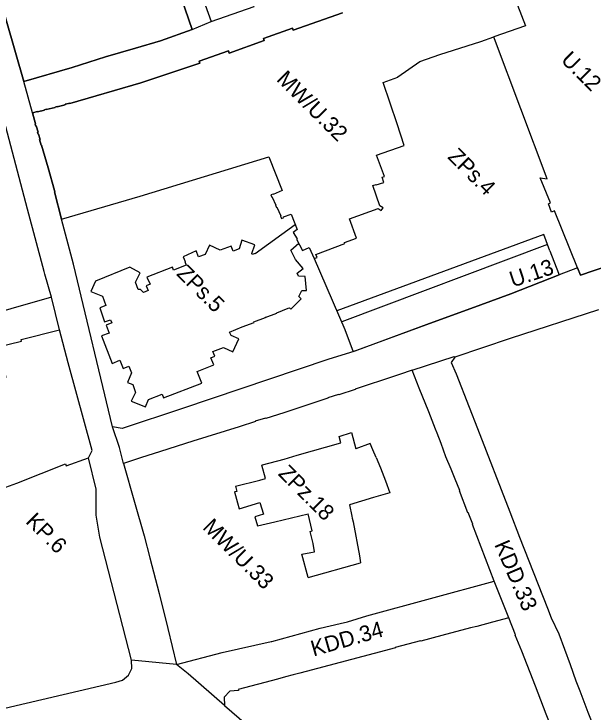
# Model space of a CAD drawing. Extents: x 7423835 to 7425280, y 5546086 to 5547600.
# Drawn here: x 7424373.9 to 7424593.5, y 5546340.4 to 5546605 of the extents above; entities that cross this region are included whole.
import ezdxf

# ---------------------------------------------------------------- set-up
doc = ezdxf.new("R2010")
doc.units = 0
for name, color, linetype in [('linie rozgraniczające', 7, 'Continuous'), ('nieprzekraczalne linie zabudowy', 7, 'Continuous'), ('obowiazujace linie zabudowy', 7, 'Continuous'), ('przeznaczenia terenów', 7, 'Continuous')]:
    doc.layers.add(name, color=color, linetype=linetype)

msp = doc.modelspace()

# ---------------------------------------------------------------- linework, layer by layer
at = {"layer": 'linie rozgraniczające'}
for p, q in [((7424441.46, 5546599.12), (7424448.69, 5546602.18)), ((7424380.94, 5546567.54), (7424377.65, 5546579.36)), ((7424587.64, 5546508.75), (7424580.62, 5546506.1)), ((7424524.96, 5546469.95), (7424540.84, 5546475.2)), ((7424540.84, 5546475.2), (7424541.11, 5546474.97)), ((7424527.63, 5546463.24), (7424524.96, 5546469.95)), ((7424485.48, 5546391.4), (7424505.36, 5546397.02)), ((7424561.54, 5546376.13), (7424556.04, 5546390.02)), ((7424435.51, 5546358.4), (7424418.49, 5546360.03))]:
    msp.add_line(p, q, dxfattribs=at)
for points in [[(7424498.22, 5546619.84), (7424492.5, 5546638.34), (7424492.84, 5546638.45), (7424491.5, 5546642.95), (7424486.43, 5546660.24), (7424483.37, 5546671.92), (7424480.11, 5546679.93), (7424468.32, 5546674.65), (7424455.33, 5546669.86), (7424428.5, 5546660.01), (7424437.17, 5546634.91), (7424441.77, 5546621.66), (7424448.69, 5546602.18), (7424464.99, 5546607.91), (7424464.93, 5546608.08), (7424487.47, 5546615.94)], [(7424415.44, 5546675.99), (7424420.93, 5546660.04), (7424421.75, 5546657.53), (7424423.79, 5546651.25), (7424427.88, 5546638.9), (7424441.46, 5546599.12), (7424429.54, 5546594.89), (7424419.97, 5546592.1), (7424408.6, 5546588.75), (7424395.96, 5546584.68), (7424377.65, 5546579.36), (7424357.5, 5546649.05), (7424367.44, 5546652.38), (7424372.88, 5546654.73), (7424377.74, 5546656.83), (7424384.62, 5546660.5)], [(7424557.12, 5546627.37), (7424559.4, 5546620.71), (7424560.48, 5546617.76), (7424561.25, 5546618.02), (7424567.94, 5546600.51), (7424555.92, 5546596.35)], [(7424391.99, 5546527.21), (7424389.27, 5546537.66), (7424389.42, 5546537.7), (7424389.3, 5546538.14), (7424386.83, 5546546.71), (7424384.36, 5546555.27), (7424384.22, 5546555.23), (7424383.61, 5546557.45), (7424383.8, 5546557.5), (7424383.2, 5546559.5), (7424383.06, 5546559.46), (7424382.86, 5546560.15), (7424383.05, 5546560.2), (7424382.33, 5546562.56), (7424382.22, 5546562.53), (7424382, 5546563.3), (7424382.12, 5546563.33), (7424380.94, 5546567.54), (7424382.81, 5546568.01), (7424382.85, 5546567.88), (7424385.46, 5546568.58), (7424385.43, 5546568.73), (7424386.13, 5546568.89), (7424386.17, 5546568.76), (7424389.56, 5546569.61), (7424389.53, 5546569.75), (7424390.24, 5546569.93), (7424390.27, 5546569.8), (7424393.37, 5546570.63), (7424393.33, 5546570.77), (7424394.59, 5546571.11), (7424395.05, 5546571.23), (7424395.09, 5546571.09), (7424422, 5546578.95), (7424444.35, 5546586.36), (7424444.17, 5546587.18), (7424455.24, 5546591.04), (7424455.47, 5546590.17), (7424468.84, 5546594.96), (7424468.57, 5546595.67), (7424479.54, 5546599.6), (7424479.78, 5546598.91), (7424498.49, 5546605.47)], [(7424391.99, 5546527.21), (7424421.79, 5546535.98), (7424470.55, 5546550.9), (7424470.55, 5546550.9), (7424475.58, 5546538.13), (7424472.2, 5546536.65), (7424472.15, 5546536.77), (7424471.31, 5546536.41), (7424471.7, 5546535.56), (7424471.81, 5546535.61), (7424473.2, 5546532.59), (7424473.1, 5546532.55), (7424473.47, 5546531.71), (7424473.59, 5546531.74), (7424475.09, 5546528.46), (7424474.98, 5546528.41), (7424475.37, 5546527.53), (7424476.25, 5546527.88), (7424476.16, 5546528.09), (7424479.01, 5546529.16), (7424481.31, 5546523.3), (7424479.78, 5546522.15), (7424481.34, 5546519.74), (7424481.1, 5546519.69), (7424483.38, 5546515.33), (7424485.86, 5546516.53), (7424487.79, 5546512.29), (7424488.85, 5546512.71), (7424488.37, 5546513.82), (7424499.39, 5546517.99), (7424499.26, 5546518.34), (7424503.8, 5546520), (7424501.16, 5546527.39), (7424511.99, 5546531.31), (7424513.21, 5546530.5), (7424513.87, 5546531.49), (7424512.68, 5546532.34), (7424509.96, 5546539.97), (7424511.24, 5546540.41), (7424511.28, 5546540.28), (7424514.21, 5546541.19), (7424513.54, 5546543.11), (7424514.43, 5546543.47), (7424511.38, 5546551.53), (7424521.92, 5546555.14), (7424519.18, 5546563.32), (7424513.92, 5546579), (7424519.52, 5546581.07), (7424519.48, 5546581.2), (7424527.86, 5546587.01), (7424535.44, 5546589.69), (7424550.96, 5546594.63), (7424555.92, 5546596.35)], [(7424587.64, 5546508.75), (7424578.86, 5546530.35), (7424577.76, 5546529.89), (7424576.56, 5546533.11), (7424577.43, 5546533.46), (7424573.5, 5546542.92), (7424576.15, 5546542.53), (7424556.19, 5546595.63), (7424555.92, 5546596.35)], [(7424385.33, 5546507.45), (7424379.08, 5546531), (7424370.16, 5546564.59), (7424342, 5546556.12), (7424329.64, 5546551.71), (7424310.79, 5546544.94), (7424310.68, 5546544.73), (7424310.61, 5546544.48), (7424310.69, 5546544.25), (7424287.1, 5546536.15)], [(7424580.62, 5546506.1), (7424562.37, 5546498.9), (7424547.13, 5546493.38), (7424531.43, 5546487.69), (7424503.15, 5546477.24), (7424492.95, 5546474.08), (7424437.88, 5546455.53), (7424414.91, 5546447.91), (7424411.3, 5546448.56), (7424396.46, 5546510.24), (7424391.99, 5546527.21)], [(7424577.18, 5546515.19), (7424574.82, 5546521.42), (7424496.32, 5546492.55)], [(7424624.19, 5546517.76), (7424593.56, 5546507.65), (7424588.76, 5546506.02), (7424587.64, 5546508.75)], [(7424577.18, 5546515.19), (7424580.38, 5546506.71), (7424580.61, 5546506.1)], [(7424487.79, 5546512.29), (7424499.37, 5546485.48), (7424502.2, 5546478.02), (7424502.56, 5546477.06)], [(7424394.5, 5546472.74), (7424391.22, 5546485.25), (7424388.19, 5546497.72), (7424385.59, 5546506.44), (7424385.33, 5546507.45)], [(7424388.19, 5546497.72), (7424357.13, 5546488.82), (7424358.24, 5546485.3)], [(7424595.52, 5546492.88), (7424562.11, 5546482.06), (7424541.11, 5546474.97), (7424539.74, 5546472.92), (7424541.62, 5546468.6), (7424546.51, 5546455.96), (7424549.64, 5546447.94), (7424561.93, 5546416.26), (7424565.58, 5546406.74), (7424576.21, 5546379.83), (7424577.6, 5546376.12), (7424580.47, 5546370.11), (7424584.82, 5546358.39), (7424587.04, 5546352.21), (7424588.52, 5546348.5), (7424591.51, 5546340.39), (7424598.75, 5546322.51)], [(7424309.97, 5546460.74), (7424314.5, 5546462.36), (7424320.52, 5546464.53), (7424328.99, 5546466.65), (7424332.85, 5546469.12), (7424335.89, 5546470.68), (7424339.01, 5546472.28), (7424339.01, 5546472.28), (7424341.59, 5546463.44), (7424337.68, 5546462.29), (7424339.65, 5546455.53), (7424346.89, 5546457.93), (7424351.28, 5546459.38), (7424350.66, 5546461.47), (7424352.59, 5546461.99), (7424362.22, 5546464.88), (7424365.62, 5546465.95), (7424368.4, 5546466.76), (7424370.9, 5546467.32), (7424369.82, 5546471.89), (7424367.79, 5546478.91), (7424376.8, 5546481.03), (7424376.65, 5546481.65), (7424391.22, 5546485.25)], [(7424326.63, 5546410.04), (7424345.67, 5546416.79), (7424345.72, 5546416.64), (7424358.22, 5546421.09), (7424374.99, 5546427.15), (7424393.4, 5546434.44), (7424393.66, 5546433.71), (7424402.17, 5546436.72), (7424403.6, 5546439.53), (7424394.5, 5546472.74)], [(7424524.96, 5546469.95), (7424520.09, 5546468.33), (7424513.25, 5546466.08), (7424508.57, 5546464.58), (7424503.32, 5546462.86), (7424503.36, 5546462.72), (7424497.06, 5546460.64), (7424497.01, 5546460.79), (7424492.95, 5546459.47), (7424492.93, 5546459.35), (7424476.22, 5546453.84), (7424469.37, 5546451.74), (7424469.33, 5546451.87), (7424465.4, 5546450.67), (7424465.44, 5546450.54), (7424459.32, 5546448.5), (7424441.73, 5546443.11), (7424432.65, 5546440.2), (7424429.15, 5546439.06), (7424422.29, 5546436.86), (7424415.44, 5546434.66), (7424419.65, 5546419.97), (7424423.26, 5546407.17), (7424425.39, 5546398.89), (7424428.97, 5546385.37), (7424432.27, 5546372.04), (7424435.51, 5546358.4), (7424452.87, 5546363), (7424471.49, 5546367.13), (7424471.75, 5546367.18), (7424490.02, 5546372.15), (7424497.56, 5546373.94), (7424500.36, 5546374.66), (7424507.7, 5546376.85), (7424556.04, 5546390.02), (7424547.76, 5546411.55), (7424547.9, 5546411.59), (7424546.19, 5546416.04), (7424546.03, 5546415.98), (7424542.82, 5546424.27), (7424542.98, 5546424.33), (7424541.28, 5546428.72), (7424539.75, 5546432.54), (7424537.71, 5546437.21), (7424535.93, 5546442.17), (7424534.37, 5546446.08), (7424533.77, 5546447.63), (7424531.23, 5546454.17), (7424527.63, 5546463.24)], [(7424415.44, 5546434.66), (7424413.96, 5546440.68), (7424411.3, 5546448.56)], [(7424457.95, 5546426.03), (7424467.09, 5546428.32), (7424469.3, 5546428.89), (7424467.96, 5546434.04), (7424468.1, 5546434.08), (7424476.36, 5546436.31), (7424481.3, 5546437.73), (7424497.83, 5546442.44), (7424497.25, 5546444.85), (7424501.9, 5546446.43), (7424503.54, 5546440.19)], [(7424509.01, 5546442.17), (7424509.01, 5546442.17), (7424503.54, 5546440.19)], [(7424511.23, 5546436.86), (7424509.97, 5546439.78), (7424509.01, 5546442.17)], [(7424329.68, 5546348.73), (7424333.41, 5546336.36), (7424335.31, 5546335.37), (7424338.04, 5546334.78), (7424340.75, 5546335.13), (7424350.4, 5546337.18), (7424412.55, 5546351.75), (7424415.01, 5546352.54), (7424417.37, 5546354.37), (7424418.62, 5546356.9), (7424418.49, 5546360.03), (7424406.49, 5546406.68), (7424405.05, 5546415.06), (7424405.06, 5546424.89), (7424402.17, 5546436.72)], [(7424511.23, 5546436.86), (7424512.91, 5546432.99), (7424514.78, 5546428.04), (7424516.49, 5546423.54), (7424510.21, 5546421.68), (7424501.11, 5546419.01), (7424502.02, 5546414.64), (7424502.19, 5546413.85), (7424502.48, 5546412.48), (7424504.96, 5546399.69), (7424505.36, 5546397.02)], [(7424457.95, 5546426.03), (7424458.4, 5546423.98), (7424457.55, 5546423.83)], [(7424457.55, 5546423.83), (7424458.65, 5546419.74), (7424459.27, 5546417.43)], [(7424459.27, 5546417.43), (7424467.13, 5546419.82), (7424468.54, 5546415.4), (7424465.29, 5546414.42), (7424466.32, 5546410.95), (7424472.87, 5546412.5), (7424485.45, 5546415.49)], [(7424487.32, 5546404.3), (7424486.29, 5546408.88), (7424486.98, 5546409.05), (7424485.45, 5546415.49)], [(7424485.48, 5546391.4), (7424483.13, 5546400.22), (7424486.49, 5546400.88), (7424487.82, 5546401.16), (7424487.32, 5546404.3)], [(7424561.54, 5546376.13), (7424555.43, 5546374.49), (7424549.44, 5546372.79), (7424547.04, 5546372.33), (7424536.22, 5546369.43), (7424528.14, 5546367.27), (7424528.09, 5546367.45), (7424518.48, 5546364.93), (7424518.53, 5546364.74), (7424510.45, 5546362.61), (7424497.58, 5546359.21), (7424484.72, 5546355.8), (7424482.28, 5546355.16), (7424479.83, 5546354.51), (7424476.83, 5546353.72), (7424473.83, 5546352.93), (7424458.96, 5546349.02), (7424459.07, 5546348.55), (7424455.83, 5546348.37), (7424453.6, 5546346.1), (7424453.79, 5546342.91), (7424466.82, 5546331.71)], [(7424552.44, 5546281.41), (7424572.67, 5546287.45), (7424572.62, 5546287.62), (7424573.12, 5546287.79), (7424591.59, 5546292.98), (7424593.44, 5546293.94), (7424587.14, 5546311.55), (7424583.54, 5546320.29), (7424575.79, 5546339.67), (7424571.69, 5546350.19), (7424566.51, 5546363.45), (7424564, 5546369.59), (7424564.15, 5546369.64), (7424561.54, 5546376.13)], [(7424453.79, 5546342.91), (7424439.92, 5546354.86), (7424435.51, 5546358.4)]]:
    msp.add_lwpolyline(points, dxfattribs=at)
at = {"layer": 'nieprzekraczalne linie zabudowy'}
for p, q in [((7424480.6, 5546525.11), (7424465.42, 5546514.14)), ((7424460.38, 5546519.24), (7424459.3, 5546516.02)), ((7424465.22, 5546517.54), (7424460.38, 5546519.24)), ((7424448.04, 5546517.35), (7424446.39, 5546513.86)), ((7424452.12, 5546515.46), (7424448.04, 5546517.35)), ((7424456.24, 5546517.06), (7424452.12, 5546515.46)), ((7424456.97, 5546515.11), (7424456.24, 5546517.06)), ((7424459.3, 5546516.02), (7424456.97, 5546515.11)), ((7424464.13, 5546514.23), (7424465.22, 5546517.54)), ((7424478.85, 5546515.48), (7424481.91, 5546518.14)), ((7424576.21, 5546517.58), (7424498.19, 5546488.28)), ((7424443.04, 5546515.19), (7424438.08, 5546512.94)), ((7424443.91, 5546512.91), (7424443.04, 5546515.19)), ((7424446.39, 5546513.86), (7424443.91, 5546512.91)), ((7424464.3, 5546513.83), (7424464.13, 5546514.23)), ((7424465.37, 5546514.25), (7424464.3, 5546513.83)), ((7424465.42, 5546514.14), (7424465.37, 5546514.25)), ((7424480.71, 5546511.99), (7424478.85, 5546515.48)), ((7424438.08, 5546512.94), (7424438.77, 5546511.22)), ((7424438.77, 5546511.22), (7424438.65, 5546511.16)), ((7424438.65, 5546511.16), (7424439.16, 5546509.76)), ((7424483.57, 5546508.51), (7424480.71, 5546511.99)), ((7424417.79, 5546509.05), (7424404.77, 5546503.78)), ((7424421.82, 5546506.94), (7424417.79, 5546509.05)), ((7424433.99, 5546509.1), (7424424.33, 5546505.31)), ((7424434.44, 5546507.97), (7424433.99, 5546509.1)), ((7424439.16, 5546509.76), (7424434.44, 5546507.97)), ((7424481.36, 5546506.77), (7424483.57, 5546508.51)), ((7424420, 5546503.33), (7424421.82, 5546506.94)), ((7424481.76, 5546505.66), (7424481.36, 5546506.77)), ((7424484.31, 5546505.56), (7424481.76, 5546505.66)), ((7424484.78, 5546500.18), (7424484.31, 5546505.56)), ((7424404.77, 5546503.78), (7424403.11, 5546499.84)), ((7424421.06, 5546500.52), (7424420, 5546503.33)), ((7424424.33, 5546505.31), (7424425.54, 5546502.55)), ((7424421.87, 5546500.54), (7424421.06, 5546500.52)), ((7424423, 5546499.49), (7424421.87, 5546500.54)), ((7424424.77, 5546500.19), (7424423, 5546499.49)), ((7424425.54, 5546502.55), (7424424.06, 5546501.94)), ((7424424.06, 5546501.94), (7424424.77, 5546500.19)), ((7424481.99, 5546497.89), (7424483.11, 5546500.23)), ((7424483.11, 5546500.23), (7424484.78, 5546500.18)), ((7424403.11, 5546499.84), (7424407.47, 5546498.01)), ((7424407.47, 5546498.01), (7424408.76, 5546494.56)), ((7424482.78, 5546497.03), (7424481.99, 5546497.89)), ((7424478.89, 5546493.18), (7424482.78, 5546497.03)), ((7424408.76, 5546494.56), (7424406.48, 5546493.67)), ((7424406.48, 5546493.67), (7424408.28, 5546488.31)), ((7424473.59, 5546491.74), (7424477.9, 5546493.48)), ((7424477.9, 5546493.48), (7424478.44, 5546493.69)), ((7424478.44, 5546493.69), (7424478.89, 5546493.18)), ((7424464.9, 5546488.27), (7424469.24, 5546489.96)), ((7424469.21, 5546490.02), (7424473.62, 5546491.65)), ((7424469.24, 5546489.96), (7424469.21, 5546490.02)), ((7424473.62, 5546491.65), (7424473.59, 5546491.74)), ((7424408.28, 5546488.31), (7424410.53, 5546489.09)), ((7424410.98, 5546487.93), (7424408.82, 5546487.06)), ((7424408.82, 5546487.06), (7424410.04, 5546484.04)), ((7424410.53, 5546489.09), (7424410.98, 5546487.93)), ((7424460.43, 5546486.42), (7424464.97, 5546488.11)), ((7424464.97, 5546488.11), (7424464.9, 5546488.27)), ((7424455.7, 5546484.46), (7424460.45, 5546486.38)), ((7424456.22, 5546483.15), (7424455.7, 5546484.46)), ((7424460.45, 5546486.38), (7424460.43, 5546486.42)), ((7424410.04, 5546484.04), (7424407.07, 5546482.96)), ((7424407.07, 5546482.96), (7424411.13, 5546472.55)), ((7424459.15, 5546481.9), (7424456.22, 5546483.15)), ((7424456.88, 5546477), (7424459.15, 5546481.9)), ((7424449.32, 5546477.09), (7424453.31, 5546478.57)), ((7424450.02, 5546475.25), (7424449.32, 5546477.09)), ((7424453.31, 5546478.57), (7424456.88, 5546477)), ((7424411.13, 5546472.55), (7424414.08, 5546473.77)), ((7424414.08, 5546473.77), (7424415.31, 5546470.64)), ((7424448.62, 5546474.71), (7424450.02, 5546475.25)), ((7424449.68, 5546472.03), (7424448.62, 5546474.71)), ((7424415.31, 5546470.64), (7424417.52, 5546471.5)), ((7424417.52, 5546471.5), (7424418.53, 5546469.03)), ((7424443.44, 5546469.51), (7424449.68, 5546472.03)), ((7424418.53, 5546469.03), (7424417.01, 5546465.38)), ((7424445.16, 5546465.07), (7424443.44, 5546469.51)), ((7424417.01, 5546465.38), (7424419.04, 5546464.55)), ((7424419.04, 5546464.55), (7424419.99, 5546461.59)), ((7424430.64, 5546459.52), (7424445.16, 5546465.07)), ((7424419.99, 5546461.59), (7424418.3, 5546458.23)), ((7424424.92, 5546458.88), (7424430.05, 5546460.88)), ((7424430.05, 5546460.88), (7424430.64, 5546459.52)), ((7424418.3, 5546458.23), (7424423.84, 5546456.11)), ((7424423.84, 5546456.11), (7424424.92, 5546458.88))]:
    msp.add_line(p, q, dxfattribs=at)
at = {"layer": 'obowiazujace linie zabudowy'}
for points in [[(7424498.22, 5546619.84), (7424492.5, 5546638.34), (7424492.84, 5546638.45), (7424491.5, 5546642.95), (7424486.43, 5546660.24), (7424483.37, 5546671.92), (7424480.11, 5546679.93), (7424468.32, 5546674.65), (7424455.33, 5546669.86), (7424428.5, 5546660.01), (7424437.17, 5546634.91), (7424441.77, 5546621.66), (7424448.69, 5546602.18), (7424464.99, 5546607.91), (7424464.93, 5546608.08), (7424487.47, 5546615.94)], [(7424367.44, 5546652.38), (7424357.5, 5546649.05), (7424377.65, 5546579.36), (7424395.96, 5546584.68), (7424408.6, 5546588.75), (7424419.97, 5546592.1), (7424429.54, 5546594.89), (7424441.46, 5546599.12), (7424427.88, 5546638.9), (7424421.71, 5546657.52)], [(7424498.49, 5546605.47), (7424479.78, 5546598.91), (7424479.54, 5546599.6), (7424468.57, 5546595.67), (7424468.84, 5546594.96), (7424455.47, 5546590.17), (7424455.24, 5546591.04), (7424444.17, 5546587.18), (7424444.35, 5546586.36), (7424422, 5546578.95), (7424395.09, 5546571.09), (7424395.05, 5546571.23), (7424394.59, 5546571.11), (7424393.33, 5546570.77), (7424393.37, 5546570.63), (7424390.27, 5546569.8), (7424390.24, 5546569.93), (7424389.53, 5546569.75), (7424389.56, 5546569.61), (7424386.17, 5546568.76), (7424386.13, 5546568.89), (7424385.43, 5546568.73), (7424385.46, 5546568.58), (7424382.85, 5546567.88), (7424382.81, 5546568.01), (7424380.94, 5546567.54), (7424382.12, 5546563.33), (7424382, 5546563.3), (7424382.22, 5546562.53), (7424382.33, 5546562.56), (7424383.05, 5546560.2), (7424382.86, 5546560.15), (7424383.06, 5546559.46), (7424383.2, 5546559.5), (7424383.8, 5546557.5), (7424383.61, 5546557.45), (7424384.22, 5546555.23), (7424384.36, 5546555.27), (7424386.83, 5546546.71), (7424389.3, 5546538.14), (7424389.42, 5546537.7), (7424389.27, 5546537.66), (7424391.99, 5546527.21)], [(7424385.33, 5546507.45), (7424379.08, 5546531), (7424370.16, 5546564.59), (7424342, 5546556.12), (7424329.64, 5546551.71), (7424310.79, 5546544.94), (7424310.68, 5546544.73), (7424310.61, 5546544.48), (7424310.69, 5546544.25), (7424287.1, 5546536.15)], [(7424587.64, 5546508.75), (7424588.76, 5546506.02), (7424593.56, 5546507.65), (7424624.19, 5546517.76)], [(7424388.19, 5546497.72), (7424385.59, 5546506.44), (7424385.33, 5546507.45)], [(7424502.58, 5546477.03), (7424531.43, 5546487.69), (7424547.13, 5546493.38), (7424562.37, 5546498.9), (7424580.62, 5546506.1)], [(7424394.5, 5546472.74), (7424391.22, 5546485.25)], [(7424326.63, 5546410.04), (7424345.67, 5546416.79), (7424345.72, 5546416.64), (7424358.22, 5546421.09), (7424374.99, 5546427.15), (7424393.4, 5546434.44), (7424393.66, 5546433.71), (7424402.17, 5546436.72), (7424403.6, 5546439.53), (7424394.5, 5546472.74)], [(7424524.96, 5546469.95), (7424520.09, 5546468.33), (7424513.25, 5546466.08), (7424508.57, 5546464.58), (7424503.32, 5546462.86), (7424503.36, 5546462.72), (7424497.06, 5546460.64), (7424497.01, 5546460.79), (7424492.95, 5546459.47), (7424492.93, 5546459.35), (7424476.22, 5546453.84), (7424469.37, 5546451.74), (7424469.33, 5546451.87), (7424465.4, 5546450.67), (7424465.44, 5546450.54), (7424459.32, 5546448.5), (7424441.73, 5546443.11), (7424432.65, 5546440.2), (7424429.15, 5546439.06), (7424422.29, 5546436.86), (7424415.44, 5546434.66), (7424419.65, 5546419.97), (7424423.26, 5546407.17), (7424425.39, 5546398.89), (7424428.97, 5546385.37), (7424432.27, 5546372.04), (7424435.51, 5546358.4), (7424452.87, 5546363), (7424471.49, 5546367.13), (7424471.75, 5546367.18), (7424490.02, 5546372.15), (7424497.56, 5546373.94), (7424500.36, 5546374.66), (7424507.7, 5546376.85), (7424556.04, 5546390.02), (7424547.76, 5546411.55), (7424547.9, 5546411.59), (7424546.19, 5546416.04), (7424546.03, 5546415.98), (7424542.82, 5546424.27), (7424542.98, 5546424.33), (7424541.28, 5546428.72), (7424539.75, 5546432.54), (7424537.71, 5546437.21), (7424535.93, 5546442.17), (7424534.37, 5546446.08), (7424533.77, 5546447.63), (7424531.23, 5546454.17), (7424527.63, 5546463.24), (7424524.96, 5546469.95)], [(7424561.54, 5546376.13), (7424555.43, 5546374.49), (7424549.44, 5546372.79), (7424547.04, 5546372.33), (7424536.22, 5546369.43), (7424528.14, 5546367.27), (7424528.09, 5546367.45), (7424518.48, 5546364.93), (7424518.53, 5546364.74), (7424510.45, 5546362.61), (7424497.58, 5546359.21), (7424484.72, 5546355.8), (7424482.28, 5546355.16), (7424479.83, 5546354.51), (7424476.83, 5546353.72), (7424473.83, 5546352.93), (7424458.96, 5546349.02), (7424459.07, 5546348.55), (7424455.83, 5546348.37), (7424453.6, 5546346.1), (7424453.79, 5546342.91), (7424466.82, 5546331.71)], [(7424552.44, 5546281.41), (7424572.67, 5546287.45), (7424572.62, 5546287.62), (7424573.12, 5546287.79), (7424591.59, 5546292.98), (7424593.44, 5546293.94), (7424587.14, 5546311.55), (7424583.54, 5546320.29), (7424575.79, 5546339.67), (7424571.69, 5546350.19), (7424566.51, 5546363.45), (7424564, 5546369.59), (7424564.15, 5546369.64), (7424561.54, 5546376.13)]]:
    msp.add_lwpolyline(points, dxfattribs=at)

# ---------------------------------------------------------------- texts
at = {"layer": 'przeznaczenia terenów'}
for s, rotation, p in [('U.12', 314.9764, (7424581.01, 5546587.26)), ('MW/U.32', 314.9764, (7424473.15, 5546579.94)), ('ZPs.4', 314.9764, (7424538.07, 5546550.55)), ('U.13', 18.3138, (7424563.03, 5546501.32)), ('ZPs.5', 314.9764, (7424435.25, 5546506.24)), ('ZPz.18', 314.9764, (7424473.77, 5546430.48)), ('KP.6', 314.9764, (7424378, 5546412.32)), ('MW/U.33', 314.9764, (7424445.14, 5546410.12)), ('KDD.33', 293.4049, (7424555.97, 5546403.93)), ('KDD.34', 16.1211, (7424487.49, 5546361.43))]:
    msp.add_text(s, height=6, rotation=rotation, dxfattribs=at).set_placement(p)

doc.saveas('drawing.dxf')
